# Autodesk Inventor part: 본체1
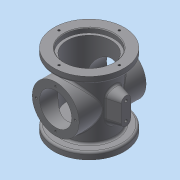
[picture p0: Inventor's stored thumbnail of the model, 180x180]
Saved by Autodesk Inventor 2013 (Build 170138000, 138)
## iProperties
Created: 2018-02
Part Number: 본체1
Material: 일반
Document SubType Name: Modeling
Designer: Administrator
Density: 1 g/cm^3
Author: Administrator
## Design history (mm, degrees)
sketch "스케치2"
  geometry: C1 r 52.5 at (0, 0); 1 further point
  constraints: 1 centre point, 1 coincident
  dimensions: "d0" = 105 diameter of C1
extrude "돌출1" new body sketch "스케치2" distance "d3" = 10; taper "d4" = 0 deg
sketch "스케치3"
  geometry: C1 r 52.5 at (0, 0) reference; C2 r 38 at (0, 0)
  constraints: 1 centre point, 1 coincident
  dimensions: "d5" = 76 diameter of C2
extrude "돌출2" join sketch "스케치3" distance "d7" = 88; taper "d8" = 0 deg
sketch "스케치4"
  geometry: C1 r 38 at (0, 0) reference; C2 r 52.5 at (0, 0)
  constraints: 1 centre point, 1 coincident
  dimensions: "d9" = 105 diameter of C2
extrude "돌출3" join sketch "스케치4" distance "d11" = 10; taper "d12" = 0 deg
sketch "스케치5"
  geometry: C1 r 52.5 at (0, 0) reference; C2 r 37 at (0, 0)
  constraints: 1 centre point, 1 coincident
  dimensions: "d13" = 74 diameter of C2
extrude "돌출4" cut sketch "스케치5" distance "d15" = 7; taper "d16" = 0 deg
sketch "스케치6"
  geometry: C1 r 37 at (0, 0) reference; C2 r 33 at (0, 0)
  constraints: 1 centre point, 1 coincident
  dimensions: "d17" = 66 diameter of C2
extrude "돌출5" cut sketch "스케치6" distance "d19" = 79; taper "d20" = 0 deg
sketch "스케치7"
  geometry: C1 r 52.5 at (0, 0) reference; C2 r 34 at (0, 0)
  constraints: 1 centre point, 1 coincident
  dimensions: "d21" = 68 diameter of C2
extrude "돌출6" cut sketch "스케치7" distance "d23" = 16; taper "d24" = 0 deg
node "작업 평면1"
sketch "스케치8"
  geometry: L1 (57.969, 54)-(-58.515, 54); L2 (-52.5, 0)-(52.5, 0) reference; L3 (0, 107.594)-(0, 0); C1 r 35 at (0, 53.797)
  constraints: 4 end point, 1 centre point, 1 horizontal, 1 midpoint, 1 perpendicular
  dimensions: "d26" = 54 distance between parallel lines of L1 L2; "d27" = 70 diameter of C1
extrude "돌출7" join sketch "스케치8" stored distance "d28" = 16; taper "d29" = 0 deg
sketch "스케치9"
  geometry: C1 r 35 at (0, 0) reference; C2 r 24 at (0, 0); 1 further point
  constraints: 1 centre point, 1 coincident
  dimensions: "d30" = 48 diameter of C2
extrude "돌출8" cut sketch "스케치9" stored distance "d32" = 16; taper "d33" = 0 deg
sketch "스케치21"
  geometry: L1 (0, 0)-(0, 45); L2 (0, 0)-(45, 0); L3 (0, 0)-(0, -45); L4 (0, 0)-(-45, 0); C1 r 52.5 at (0, 0) reference; C2 r 2 at (0, 45); C3 r 2 at (-45, 0); C4 r 2 at (45, 0); C5 r 2 at (0, -45); A1 r 45 centre (0, 0) between (0, 45) and (45, 0)
  constraints: 8 end point, 5 centre point, 5 coincident, 4 point on circle, 3 perpendicular, 1 vertical
  dimensions: "d60" = 90 diameter of A1; "d62" = 4 diameter of C2; "d63" = 4 diameter of C3; "d64" = 4 diameter of C4; "d65" = 4 diameter of C5
hole "구멍1" sketch "스케치21" at (-45, 0), (0, 45), (45, 0), (0, -45) diameter "d66" = 3.242; stored, may be unused: countersink angle "d70" = 90 deg, drill point angle "d72" = 118 deg; dims "d67" = 4, "d68" = 4, "d69" = 2, "d71" = 6
sketch "스케치22"
  geometry: 1 further point
sketch "스케치23"
  geometry: C1 r 34 at (0, 0) reference; C2 r 5 at (0, 0)
  constraints: 1 centre point, 1 coincident
  dimensions: "d73" = 10 diameter of C2
extrude "돌출10" cut sketch "스케치23" stored distance "d75" = 16; taper "d76" = 0 deg
node "작업 평면6"
sketch "스케치24"
  geometry: L1 (-50, 88.797)-(-50, 18.797) reference; L2 (50, 88.797)-(50, 18.797) reference; L3 (52.5, 108)-(-52.5, 108) reference; L4 (-52.5, 0)-(52.5, 0) reference; L5 (-50, 53.797)-(50, 53.797); L6 (0, 108)-(0, 0); L7 (-7, 66.797)-(-7, 40.797); L8 (7, 66.797)-(7, 40.797); A1 r 7 centre (0, 66.797) between (7, 66.797) and (-7, 66.797); A2 r 7 centre (0, 40.797) between (-7, 40.797) and (7, 40.797)
  constraints: 8 end point, 4 point on circle, 3 midpoint, 3 tangent, 2 centre point, 2 point on line, 1 parallel, 1 perpendicular
  dimensions: "d82" = 14 diameter of A1; "d83" = 13 distance from line of L5 A1.centre; "d84" = 14 diameter of A2; "d85" = 13 distance from line of L5 A2.centre
extrude "돌출11" join sketch "스케치24" stored distance "d86" = 16; taper "d87" = 15 deg
fillet "모깎기2" dims "d88" = 3
fillet "모깎기3" dims "d89" = 3
fillet "모깎기4" dims "d90" = 3
node "작업 평면7"
sketch "스케치25"
  geometry: C1 r 2.5 at (-66.797, 0); C2 r 2.5 at (-40.797, 0); A1 r 7 centre (-66.797, 0) between (-66.797, 7) and (-66.797, -7) reference; A2 r 7 centre (-40.797, 0) between (-40.797, -7) and (-40.797, 7) reference; 1 further point
  constraints: 2 centre point, 2 coincident
  dimensions: "d92" = 5 diameter of C1; "d94" = 5 diameter of C2
hole "구멍2" sketch "스케치25" at (-66.797, 0), (-40.797, 0) diameter "d95" = 4.134; stored, may be unused: countersink angle "d99" = 90 deg, drill point angle "d101" = 118 deg; dims "d96" = 6, "d97" = 4, "d98" = 2, "d100" = 8
chamfer "모따기1" distance "d103" = 1; stored, may be unused: second distance "d104" = 2, angle "d105" = 45 deg
fillet "모깎기5" dims "d106" = 3
sketch "스케치27" dims "d107" = 58
  geometry: L1 (0, 0)-(0, 29); C1 r 24 at (0, 0) reference; C2 r 35 at (0, 0) reference; C3 r 2 at (0, 29); C4 r 2 at (-29, 0); C5 r 2 at (0, -29); C6 r 2 at (29, 0); 1 further point
  constraints: 4 centre point, 2 coincident, 2 end point, 1 vertical, 1 vertical alignment, 11 other
  dimensions: "d109" = 4 diameter of C3; "d112" = 360 deg dimension on C1.centre C3.centre (derived)
hole "구멍3" sketch "스케치27" at (0, 29), (29, 0), (0, -29), (-29, 0) diameter "d114" = 3.242; stored, may be unused: countersink angle "d118" = 90 deg, drill point angle "d120" = 118 deg; dims "d115" = 6, "d116" = 4, "d117" = 2, "d119" = 8
node "솔리드1"
mirror "대칭1"
mirror "대칭2"
mirror "대칭3"
node "작업 평면8"
other parameters: "d77" = 55, "d91" = 54
